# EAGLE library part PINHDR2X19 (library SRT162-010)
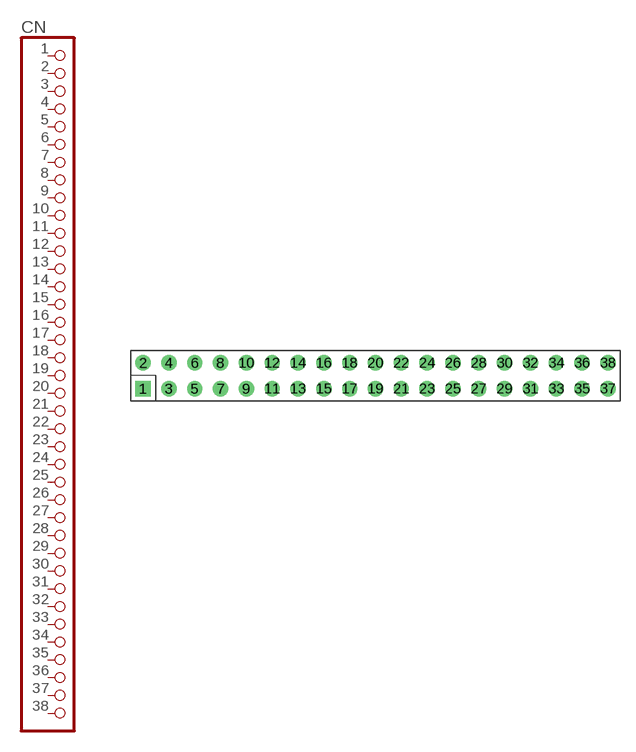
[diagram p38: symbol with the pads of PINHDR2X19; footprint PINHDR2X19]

Designator prefix CN

## PINHDR2X19  [PINHDR2X19]
1  1  pas
2  2  pas
3  3  pas
4  4  pas
5  5  pas
6  6  pas
7  7  pas
8  8  pas
9  9  pas
10  10  pas
11  11  pas
12  12  pas
13  13  pas
14  14  pas
15  15  pas
16  16  pas
17  17  pas
18  18  pas
19  19  pas
20  20  pas
21  21  pas
22  22  pas
23  23  pas
24  24  pas
25  25  pas
26  26  pas
27  27  pas
28  28  pas
29  29  pas
30  30  pas
31  31  pas
32  32  pas
33  33  pas
34  34  pas
35  35  pas
36  36  pas
37  37  pas
38  38  pas

## Footprint PINHDR2X19 (pad centres in mm)
drill 1 square: 1 -22.86,-1.27
drill 1 round: 2 -22.86,1.27; 3 -20.32,-1.27; 4 -20.32,1.27; 5 -17.78,-1.27; 6 -17.78,1.27; 7 -15.24,-1.27; 8 -15.24,1.27; 9 -12.7,-1.27; 10 -12.7,1.27; 11 -10.16,-1.27; 12 -10.16,1.27; 13 -7.62,-1.27; 14 -7.62,1.27; 15 -5.08,-1.27; 16 -5.08,1.27; 17 -2.54,-1.27; 18 -2.54,1.27; 19 0,-1.27; 20 0,1.27; 21 2.54,-1.27; 22 2.54,1.27; 23 5.08,-1.27; 24 5.08,1.27; 25 7.62,-1.27; 26 7.62,1.27; 27 10.16,-1.27; 28 10.16,1.27; 29 12.7,-1.27; 30 12.7,1.27; 31 15.24,-1.27; 32 15.24,1.27; 33 17.78,-1.27; 34 17.78,1.27; 35 20.32,-1.27; 36 20.32,1.27; 37 22.86,-1.27; 38 22.86,1.27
